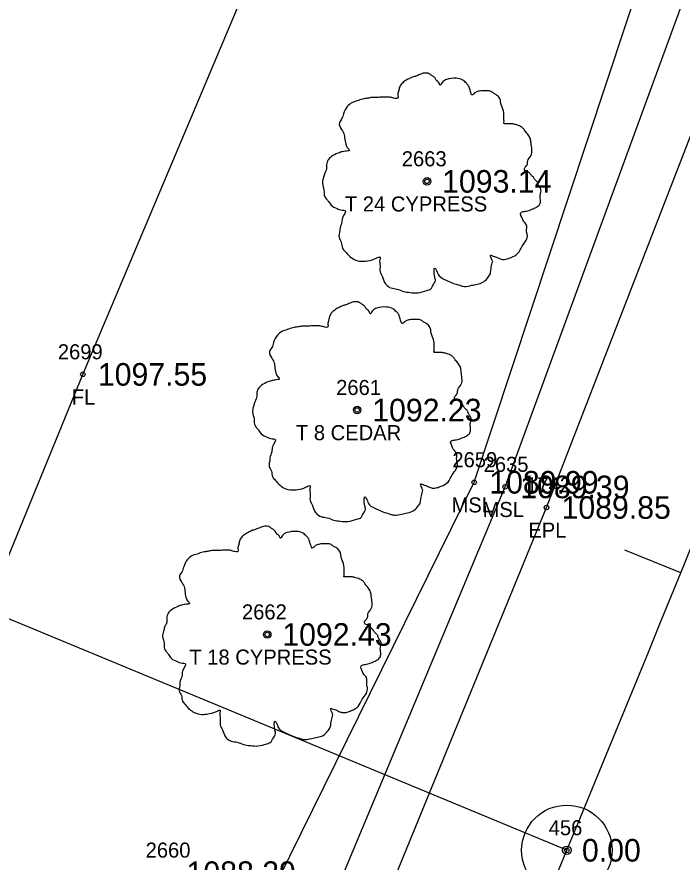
# Model space of a CAD drawing. Extents: x 1578957 to 1581675, y 1115963 to 1120391.
# Drawn here: x 1580656.7 to 1580700.8, y 1119254.9 to 1119311 of the extents above; entities that cross this region are included whole.
import ezdxf

# ---------------------------------------------------------------- set-up
doc = ezdxf.new("R2010")
doc.units = 0
for name, color, linetype in [('RD_EX_Fence_Other', 7, 'Continuous'), ('RD_EX_Fence_Other_txCode', 7, 'Continuous'), ('RD_EX_Misc', 7, 'Continuous'), ('RD_EX_Misc_txCode', 7, 'Continuous'), ('RD_EX_Road', 7, 'Continuous'), ('RD_EX_Road_txCode', 7, 'Continuous'), ('RD_EX_TX_Fence_Other_ELEV', 7, 'Continuous'), ('RD_EX_TX_Misc_ELEV', 7, 'Continuous'), ('RD_EX_TX_Road_ELEV', 7, 'Continuous'), ('RD_EX_TX_VEG_ELEV', 7, 'Continuous'), ('RD_EX_VEG', 7, 'Continuous'), ('RD_EX_VEG_txCode', 7, 'Continuous'), ('RD_HC_Cl', 7, 'Continuous'), ('RD_HC_Data', 7, 'Continuous'), ('RD_HC_Data_Tic', 7, 'Continuous'), ('RD_HC_Survey_ELEV', 7, 'Continuous'), ('RD_HC_txCode', 7, 'Continuous'), ('RD_SMD_Locator', 7, 'Continuous')]:
    doc.layers.add(name, color=color, linetype=linetype)

msp = doc.modelspace()

# ---------------------------------------------------------------- linework, layer by layer
at = {"layer": 'RD_EX_Fence_Other'}
msp.add_lwpolyline([(1580513.827, 1119078.662), (1580554.331, 1119026.263), (1580554.331, 1119026.263), (1580661.056, 1119287.238), (1580681.048, 1119334.68), (1580698.952, 1119378.888), (1580718.027, 1119424.961), (1580737.744, 1119473.232)], dxfattribs=at)
at = {"layer": 'RD_EX_Misc'}
for points in [[(1580575.469, 1119001.964), (1580572.192, 1119003.299), (1580573.344, 1119008.973), (1580569.078, 1119017.528), (1580583.69, 1119050.381), (1580599.817, 1119098.808), (1580624.045, 1119165.829), (1580641.396, 1119195.473), (1580666.371, 1119238.149), (1580687.021, 1119280.073), (1580703.349, 1119329.398), (1580719.477, 1119374.249), (1580736.36, 1119422.972), (1580751.158, 1119471.49)], [(1580572.228, 1119003.293), (1580577.641, 1119002.275), (1580593.887, 1119048.73), (1580611.465, 1119096.441), (1580629.396, 1119141.91), (1580650.31, 1119188.617), (1580669.532, 1119232.972), (1580689.078, 1119279.767), (1580706.148, 1119326.435), (1580722.862, 1119373.532), (1580740.07, 1119420.2), (1580755.304, 1119467.381)]]:
    msp.add_lwpolyline(points, dxfattribs=at)
at = {"layer": 'RD_EX_Road'}
msp.add_lwpolyline([(1580561.509, 1118902.856), (1580569.284, 1118952.033), (1580572.257, 1118964.729), (1580572.024, 1118971.684), (1580570.785, 1118976.943), (1580576.68, 1118999.159), (1580578.916, 1119000.71), (1580583.17, 1119008.339), (1580597.232, 1119047.928), (1580615.21, 1119094.659), (1580634.106, 1119140.594), (1580653.543, 1119186.411), (1580672.941, 1119232.27), (1580691.817, 1119278.399), (1580709.783, 1119324.767), (1580727.167, 1119371.358), (1580744.517, 1119418.33), (1580760.444, 1119465.683)], dxfattribs=at)
at = {"layer": 'RD_EX_VEG'}
for centre, radius in [((1580683.895, 1119300.053), 0.25), ((1580683.882, 1119300.034), 0.0001), ((1580679.258, 1119284.869), 0.25), ((1580679.245, 1119284.85), 0.0001), ((1580673.292, 1119269.969), 0.25), ((1580673.279, 1119269.95), 0.0001)]:
    msp.add_circle(centre, radius, dxfattribs=at)
for points in [[(1580684.027, 1119307.22), (1580683.727, 1119307.245), (1580683.402, 1119307.145), (1580683.152, 1119307.045), (1580682.927, 1119306.97), (1580682.702, 1119306.87), (1580682.402, 1119306.696), (1580682.177, 1119306.496), (1580682.052, 1119306.246), (1580682.002, 1119306.021), (1580681.953, 1119305.746), (1580681.953, 1119305.571), (1580681.828, 1119305.546), (1580681.678, 1119305.571), (1580681.428, 1119305.646), (1580681.178, 1119305.646), (1580680.928, 1119305.646), (1580680.578, 1119305.621), (1580680.228, 1119305.621), (1580679.953, 1119305.571), (1580679.629, 1119305.521), (1580679.254, 1119305.396), (1580678.904, 1119305.271), (1580678.604, 1119305.021), (1580678.354, 1119304.546), (1580678.229, 1119304.197), (1580678.079, 1119303.947), (1580678.229, 1119303.497), (1580678.404, 1119303.147), (1580678.429, 1119302.947), (1580678.504, 1119302.522), (1580678.604, 1119302.297), (1580678.729, 1119302.097), (1580678.654, 1119302.073), (1580678.279, 1119302.023), (1580677.979, 1119301.923), (1580677.554, 1119301.698), (1580677.33, 1119301.473), (1580677.23, 1119301.148), (1580677.205, 1119300.798), (1580677.105, 1119300.598), (1580677.03, 1119300.323), (1580677.005, 1119300.248), (1580676.955, 1119299.923), (1580677.055, 1119299.474), (1580677.08, 1119299.124), (1580677.205, 1119298.899), (1580677.355, 1119298.724), (1580677.529, 1119298.474), (1580677.929, 1119298.249), (1580678.254, 1119298.149), (1580678.454, 1119298.124), (1580678.279, 1119297.624), (1580678.229, 1119297.275), (1580678.104, 1119296.875), (1580678.104, 1119296.8), (1580678.054, 1119296.325), (1580678.204, 1119296), (1580678.279, 1119295.625), (1580678.454, 1119295.4), (1580678.729, 1119295.101), (1580679.054, 1119294.876), (1580679.554, 1119294.751), (1580679.953, 1119294.776), (1580680.528, 1119294.951), (1580680.778, 1119295.026), (1580680.753, 1119294.851), (1580680.778, 1119294.476), (1580680.778, 1119294.051), (1580680.928, 1119293.726), (1580681.028, 1119293.451), (1580681.178, 1119293.201), (1580681.503, 1119292.977), (1580681.903, 1119292.902), (1580682.327, 1119292.752), (1580682.777, 1119292.677), (1580683.277, 1119292.652), (1580683.877, 1119292.802), (1580684.152, 1119292.927), (1580684.252, 1119293.101), (1580684.451, 1119293.476), (1580684.401, 1119293.701), (1580684.426, 1119294.301), (1580684.526, 1119294.126), (1580684.701, 1119293.776), (1580685.201, 1119293.476), (1580685.601, 1119293.301), (1580686.076, 1119293.151), (1580686.376, 1119293.076), (1580686.85, 1119293.151), (1580687.225, 1119293.226), (1580687.6, 1119293.351), (1580687.9, 1119293.626), (1580688.075, 1119293.901), (1580688.125, 1119294.176), (1580688.2, 1119294.551), (1580688.25, 1119294.726)], [(1580688.25, 1119294.726), (1580688.175, 1119294.901), (1580688.125, 1119295.151), (1580688.2, 1119295.126), (1580688.375, 1119295.076), (1580688.65, 1119294.951), (1580688.875, 1119294.876), (1580689.199, 1119294.901), (1580689.474, 1119295.001), (1580689.924, 1119295.276), (1580690.199, 1119295.75), (1580690.474, 1119296.15), (1580690.549, 1119296.475), (1580690.499, 1119296.7), (1580690.474, 1119297.2), (1580690.274, 1119297.45), (1580690.224, 1119297.574), (1580690.124, 1119297.974), (1580690.199, 1119298.024), (1580690.474, 1119298.074), (1580690.849, 1119298.199), (1580691.124, 1119298.324), (1580691.348, 1119298.499), (1580691.423, 1119298.724), (1580691.398, 1119299.124), (1580691.448, 1119299.524), (1580691.373, 1119299.674), (1580691.273, 1119299.823), (1580691.198, 1119300.023), (1580691.049, 1119300.173), (1580690.949, 1119300.323), (1580690.849, 1119300.423), (1580690.724, 1119300.573), (1580690.549, 1119300.698), (1580690.399, 1119300.748), (1580690.349, 1119300.898), (1580690.499, 1119301.098), (1580690.549, 1119301.198), (1580690.574, 1119301.423), (1580690.799, 1119301.773), (1580690.849, 1119302.172), (1580690.799, 1119302.597), (1580690.749, 1119302.872), (1580690.599, 1119303.147), (1580690.399, 1119303.397), (1580690.274, 1119303.572), (1580690.099, 1119303.697), (1580689.774, 1119303.822), (1580689.524, 1119303.872), (1580689.174, 1119303.872), (1580688.974, 1119303.922), (1580688.999, 1119303.972), (1580688.999, 1119304.122), (1580688.999, 1119304.397), (1580688.924, 1119304.846), (1580688.775, 1119305.346), (1580688.775, 1119305.371), (1580688.675, 1119305.621), (1580688.45, 1119305.821), (1580688.275, 1119305.921), (1580688.075, 1119306.046), (1580687.825, 1119306.071), (1580687.525, 1119306.071), (1580687.25, 1119306.021), (1580687.05, 1119305.921), (1580686.875, 1119305.796), (1580686.8, 1119305.946), (1580686.7, 1119306.246), (1580686.65, 1119306.396), (1580686.501, 1119306.571), (1580686.276, 1119306.77), (1580685.826, 1119306.895), (1580685.201, 1119306.82), (1580684.901, 1119306.621), (1580684.751, 1119306.446), (1580684.701, 1119306.571), (1580684.501, 1119306.77), (1580684.401, 1119306.945), (1580684.227, 1119307.07), (1580684.077, 1119307.17), (1580683.977, 1119307.22)], [(1580679.39, 1119292.036), (1580679.09, 1119292.061), (1580678.765, 1119291.961), (1580678.515, 1119291.862), (1580678.29, 1119291.787), (1580678.065, 1119291.687), (1580677.766, 1119291.512), (1580677.541, 1119291.312), (1580677.416, 1119291.062), (1580677.366, 1119290.837), (1580677.316, 1119290.562), (1580677.316, 1119290.387), (1580677.191, 1119290.362), (1580677.041, 1119290.387), (1580676.791, 1119290.462), (1580676.541, 1119290.462), (1580676.291, 1119290.462), (1580675.941, 1119290.437), (1580675.591, 1119290.437), (1580675.317, 1119290.387), (1580674.992, 1119290.337), (1580674.617, 1119290.212), (1580674.267, 1119290.087), (1580673.967, 1119289.837), (1580673.717, 1119289.363), (1580673.592, 1119289.013), (1580673.442, 1119288.763), (1580673.592, 1119288.313), (1580673.767, 1119287.963), (1580673.792, 1119287.763), (1580673.867, 1119287.339), (1580673.967, 1119287.114), (1580674.092, 1119286.914), (1580674.017, 1119286.889), (1580673.642, 1119286.839), (1580673.342, 1119286.739), (1580672.918, 1119286.514), (1580672.693, 1119286.289), (1580672.593, 1119285.964), (1580672.568, 1119285.614), (1580672.468, 1119285.414), (1580672.393, 1119285.139), (1580672.368, 1119285.064), (1580672.318, 1119284.74), (1580672.418, 1119284.29), (1580672.443, 1119283.94), (1580672.568, 1119283.715), (1580672.718, 1119283.54), (1580672.893, 1119283.29), (1580673.292, 1119283.065), (1580673.617, 1119282.965), (1580673.817, 1119282.94), (1580673.642, 1119282.441), (1580673.592, 1119282.091), (1580673.467, 1119281.691), (1580673.467, 1119281.616), (1580673.417, 1119281.141), (1580673.567, 1119280.816), (1580673.642, 1119280.442), (1580673.817, 1119280.217), (1580674.092, 1119279.917), (1580674.417, 1119279.692), (1580674.917, 1119279.567), (1580675.317, 1119279.592), (1580675.891, 1119279.767), (1580676.141, 1119279.842), (1580676.116, 1119279.667), (1580676.141, 1119279.292), (1580676.141, 1119278.867), (1580676.291, 1119278.542), (1580676.391, 1119278.267), (1580676.541, 1119278.018), (1580676.866, 1119277.793), (1580677.266, 1119277.718), (1580677.691, 1119277.568), (1580678.14, 1119277.493), (1580678.64, 1119277.468), (1580679.24, 1119277.618), (1580679.515, 1119277.743), (1580679.615, 1119277.918), (1580679.815, 1119278.292), (1580679.765, 1119278.517), (1580679.79, 1119279.117), (1580679.89, 1119278.942), (1580680.065, 1119278.592), (1580680.564, 1119278.292), (1580680.964, 1119278.118), (1580681.439, 1119277.968), (1580681.739, 1119277.893), (1580682.214, 1119277.968), (1580682.588, 1119278.043), (1580682.963, 1119278.168), (1580683.263, 1119278.442), (1580683.438, 1119278.717), (1580683.488, 1119278.992), (1580683.563, 1119279.367), (1580683.613, 1119279.542)], [(1580683.613, 1119279.542), (1580683.538, 1119279.717), (1580683.488, 1119279.967), (1580683.563, 1119279.942), (1580683.738, 1119279.892), (1580684.013, 1119279.767), (1580684.238, 1119279.692), (1580684.563, 1119279.717), (1580684.837, 1119279.817), (1580685.287, 1119280.092), (1580685.562, 1119280.566), (1580685.837, 1119280.966), (1580685.912, 1119281.291), (1580685.862, 1119281.516), (1580685.837, 1119282.016), (1580685.637, 1119282.266), (1580685.587, 1119282.391), (1580685.487, 1119282.79), (1580685.562, 1119282.84), (1580685.837, 1119282.89), (1580686.212, 1119283.015), (1580686.487, 1119283.14), (1580686.712, 1119283.315), (1580686.787, 1119283.54), (1580686.762, 1119283.94), (1580686.812, 1119284.34), (1580686.737, 1119284.49), (1580686.637, 1119284.64), (1580686.562, 1119284.84), (1580686.412, 1119284.989), (1580686.312, 1119285.139), (1580686.212, 1119285.239), (1580686.087, 1119285.389), (1580685.912, 1119285.514), (1580685.762, 1119285.564), (1580685.712, 1119285.714), (1580685.862, 1119285.914), (1580685.912, 1119286.014), (1580685.937, 1119286.239), (1580686.162, 1119286.589), (1580686.212, 1119286.989), (1580686.162, 1119287.413), (1580686.112, 1119287.688), (1580685.962, 1119287.963), (1580685.762, 1119288.213), (1580685.637, 1119288.388), (1580685.462, 1119288.513), (1580685.137, 1119288.638), (1580684.887, 1119288.688), (1580684.538, 1119288.688), (1580684.338, 1119288.738), (1580684.363, 1119288.788), (1580684.363, 1119288.938), (1580684.363, 1119289.213), (1580684.288, 1119289.662), (1580684.138, 1119290.162), (1580684.138, 1119290.187), (1580684.038, 1119290.437), (1580683.813, 1119290.637), (1580683.638, 1119290.737), (1580683.438, 1119290.862), (1580683.188, 1119290.887), (1580682.888, 1119290.887), (1580682.613, 1119290.837), (1580682.413, 1119290.737), (1580682.239, 1119290.612), (1580682.164, 1119290.762), (1580682.064, 1119291.062), (1580682.014, 1119291.212), (1580681.864, 1119291.387), (1580681.639, 1119291.587), (1580681.189, 1119291.712), (1580680.564, 1119291.637), (1580680.264, 1119291.437), (1580680.114, 1119291.262), (1580680.065, 1119291.387), (1580679.865, 1119291.587), (1580679.765, 1119291.762), (1580679.59, 1119291.887), (1580679.44, 1119291.986), (1580679.34, 1119292.036)], [(1580673.424, 1119277.136), (1580673.124, 1119277.161), (1580672.799, 1119277.061), (1580672.549, 1119276.961), (1580672.324, 1119276.886), (1580672.099, 1119276.786), (1580671.799, 1119276.611), (1580671.574, 1119276.411), (1580671.449, 1119276.161), (1580671.399, 1119275.936), (1580671.35, 1119275.661), (1580671.35, 1119275.486), (1580671.225, 1119275.461), (1580671.075, 1119275.486), (1580670.825, 1119275.561), (1580670.575, 1119275.561), (1580670.325, 1119275.561), (1580669.975, 1119275.536), (1580669.625, 1119275.536), (1580669.35, 1119275.486), (1580669.026, 1119275.437), (1580668.651, 1119275.312), (1580668.301, 1119275.187), (1580668.001, 1119274.937), (1580667.751, 1119274.462), (1580667.626, 1119274.112), (1580667.476, 1119273.862), (1580667.626, 1119273.412), (1580667.801, 1119273.063), (1580667.826, 1119272.863), (1580667.901, 1119272.438), (1580668.001, 1119272.213), (1580668.126, 1119272.013), (1580668.051, 1119271.988), (1580667.676, 1119271.938), (1580667.376, 1119271.838), (1580666.951, 1119271.613), (1580666.727, 1119271.388), (1580666.627, 1119271.063), (1580666.602, 1119270.714), (1580666.502, 1119270.514), (1580666.427, 1119270.239), (1580666.402, 1119270.164), (1580666.352, 1119269.839), (1580666.452, 1119269.389), (1580666.477, 1119269.039), (1580666.602, 1119268.814), (1580666.752, 1119268.64), (1580666.926, 1119268.39), (1580667.326, 1119268.165), (1580667.651, 1119268.065), (1580667.851, 1119268.04), (1580667.676, 1119267.54), (1580667.626, 1119267.19), (1580667.501, 1119266.79), (1580667.501, 1119266.715), (1580667.451, 1119266.241), (1580667.601, 1119265.916), (1580667.676, 1119265.541), (1580667.851, 1119265.316), (1580668.126, 1119265.016), (1580668.451, 1119264.791), (1580668.951, 1119264.666), (1580669.35, 1119264.691), (1580669.925, 1119264.866), (1580670.175, 1119264.941), (1580670.15, 1119264.766), (1580670.175, 1119264.391), (1580670.175, 1119263.967), (1580670.325, 1119263.642), (1580670.425, 1119263.367), (1580670.575, 1119263.117), (1580670.9, 1119262.892), (1580671.3, 1119262.817), (1580671.724, 1119262.667), (1580672.174, 1119262.592), (1580672.674, 1119262.567), (1580673.274, 1119262.717), (1580673.549, 1119262.842), (1580673.649, 1119263.017), (1580673.848, 1119263.392), (1580673.798, 1119263.617), (1580673.823, 1119264.216), (1580673.923, 1119264.041), (1580674.098, 1119263.692), (1580674.598, 1119263.392), (1580674.998, 1119263.217), (1580675.473, 1119263.067), (1580675.773, 1119262.992), (1580676.247, 1119263.067), (1580676.622, 1119263.142), (1580676.997, 1119263.267), (1580677.297, 1119263.542), (1580677.472, 1119263.817), (1580677.522, 1119264.091), (1580677.597, 1119264.466), (1580677.647, 1119264.641)], [(1580677.647, 1119264.641), (1580677.572, 1119264.816), (1580677.522, 1119265.066), (1580677.597, 1119265.041), (1580677.772, 1119264.991), (1580678.047, 1119264.866), (1580678.272, 1119264.791), (1580678.596, 1119264.816), (1580678.871, 1119264.916), (1580679.321, 1119265.191), (1580679.596, 1119265.666), (1580679.871, 1119266.066), (1580679.946, 1119266.39), (1580679.896, 1119266.615), (1580679.871, 1119267.115), (1580679.671, 1119267.365), (1580679.621, 1119267.49), (1580679.521, 1119267.89), (1580679.596, 1119267.94), (1580679.871, 1119267.99), (1580680.246, 1119268.115), (1580680.521, 1119268.24), (1580680.745, 1119268.415), (1580680.82, 1119268.64), (1580680.795, 1119269.039), (1580680.845, 1119269.439), (1580680.77, 1119269.589), (1580680.67, 1119269.739), (1580680.595, 1119269.939), (1580680.446, 1119270.089), (1580680.346, 1119270.239), (1580680.246, 1119270.339), (1580680.121, 1119270.489), (1580679.946, 1119270.614), (1580679.796, 1119270.664), (1580679.746, 1119270.814), (1580679.896, 1119271.013), (1580679.946, 1119271.113), (1580679.971, 1119271.338), (1580680.196, 1119271.688), (1580680.246, 1119272.088), (1580680.196, 1119272.513), (1580680.146, 1119272.788), (1580679.996, 1119273.063), (1580679.796, 1119273.312), (1580679.671, 1119273.487), (1580679.496, 1119273.612), (1580679.171, 1119273.737), (1580678.921, 1119273.787), (1580678.571, 1119273.787), (1580678.371, 1119273.837), (1580678.396, 1119273.887), (1580678.396, 1119274.037), (1580678.396, 1119274.312), (1580678.321, 1119274.762), (1580678.172, 1119275.262), (1580678.172, 1119275.287), (1580678.072, 1119275.536), (1580677.847, 1119275.736), (1580677.672, 1119275.836), (1580677.472, 1119275.961), (1580677.222, 1119275.986), (1580676.922, 1119275.986), (1580676.647, 1119275.936), (1580676.447, 1119275.836), (1580676.272, 1119275.711), (1580676.197, 1119275.861), (1580676.097, 1119276.161), (1580676.047, 1119276.311), (1580675.898, 1119276.486), (1580675.673, 1119276.686), (1580675.223, 1119276.811), (1580674.598, 1119276.736), (1580674.298, 1119276.536), (1580674.148, 1119276.361), (1580674.098, 1119276.486), (1580673.898, 1119276.686), (1580673.798, 1119276.861), (1580673.624, 1119276.986), (1580673.474, 1119277.086), (1580673.374, 1119277.136)]]:
    msp.add_spline(points, degree=3, dxfattribs=at)
at = {"layer": 'RD_HC_Cl'}
msp.add_line((1580616.29, 1119070.334), (1580693.17, 1119255.64), dxfattribs=at)
msp.add_arc((1578340.815, 1120231.591), 2546.774, 337.467285, 340.391325, dxfattribs=at)
at = {"layer": 'RD_HC_Data'}
msp.add_line((1580693.17, 1119255.64), (1580585.388, 1119300.356), dxfattribs=at)
for radius in [3, 0.282]:
    msp.add_circle((1580693.17, 1119255.64), radius, dxfattribs=at)
at = {"layer": 'RD_HC_Data_Tic'}
msp.add_line((1580700.728, 1119274.061), (1580697.022, 1119275.565), dxfattribs=at)
at = {"layer": 'RD_SMD_Locator'}
for centre in [(1580683.895, 1119300.053), (1580661.056, 1119287.238), (1580679.258, 1119284.869), (1580687.021, 1119280.073), (1580689.078, 1119279.767), (1580691.817, 1119278.399), (1580673.292, 1119269.969), (1580693.17, 1119255.64)]:
    msp.add_circle(centre, 0.15, dxfattribs=at)

# ---------------------------------------------------------------- texts
at = {"layer": 'RD_EX_Fence_Other_txCode'}
for s, p in [('2699', (1580659.402, 1119288.238)), ('FL', (1580660.324, 1119285.238))]:
    msp.add_text(s, height=1, dxfattribs=at).set_placement(p)
at = {"layer": 'RD_EX_Misc_txCode'}
for s, p in [('2659', (1580685.575, 1119281.073)), ('2635', (1580687.649, 1119280.767)), ('MSL', (1580685.519, 1119278.073)), ('MSL', (1580687.575, 1119277.767))]:
    msp.add_text(s, height=1, dxfattribs=at).set_placement(p)
at = {"layer": 'RD_EX_Road_txCode'}
for s, p in [('1742', (1580690.471, 1119279.399)), ('EPL', (1580690.612, 1119276.399))]:
    msp.add_text(s, height=1, dxfattribs=at).set_placement(p)
at = {"layer": 'RD_EX_TX_Fence_Other_ELEV'}
msp.add_text('1097.55', height=1.5, dxfattribs=at).set_placement((1580662.056, 1119286.488))
at = {"layer": 'RD_EX_TX_Misc_ELEV'}
for s, p in [('1089.99', (1580688.021, 1119279.323)), ('1089.39', (1580690.078, 1119279.017))]:
    msp.add_text(s, height=1.5, dxfattribs=at).set_placement(p)
at = {"layer": 'RD_EX_TX_Road_ELEV'}
msp.add_text('1089.85', height=1.5, dxfattribs=at).set_placement((1580692.817, 1119277.649))
at = {"layer": 'RD_EX_TX_VEG_ELEV'}
for s, p in [('1093.14', (1580684.895, 1119299.303)), ('1092.23', (1580680.258, 1119284.119)), ('1092.43', (1580674.292, 1119269.219)), ('1088.29', (1580667.94, 1119253.404))]:
    msp.add_text(s, height=1.5, dxfattribs=at).set_placement(p)
at = {"layer": 'RD_EX_VEG_txCode'}
for s, p in [('2663', (1580682.218, 1119301.053)), ('T 24 CYPRESS', (1580678.446, 1119298.053)), ('2661', (1580677.864, 1119285.869)), ('T 8 CEDAR', (1580675.195, 1119282.869)), ('2662', (1580671.615, 1119270.969)), ('T 18 CYPRESS', (1580668.126, 1119267.969)), ('2660', (1580665.224, 1119255.154))]:
    msp.add_text(s, height=1, dxfattribs=at).set_placement(p)
at = {"layer": 'RD_HC_Survey_ELEV'}
msp.add_text('0.00', height=1.5, dxfattribs=at).set_placement((1580694.17, 1119254.89))
at = {"layer": 'RD_HC_txCode'}
msp.add_text('456', height=1, dxfattribs=at).set_placement((1580691.965, 1119256.64))

doc.saveas('drawing.dxf')
